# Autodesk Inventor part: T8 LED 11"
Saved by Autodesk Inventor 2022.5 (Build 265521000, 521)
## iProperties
Created: 2025-02
Part Number: T8 LED 11"
Material: Generic
Document SubType Name: Modeling
Designer: AdminForWorker
Density: 1 g/cm^3
Appearance: Default
Title: T8 LED 11" v2
Author: AdminForWorker
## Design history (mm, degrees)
feature "Body1"
feature "E26 Base" [Body]
body "Solid1"
body "Solid2"
